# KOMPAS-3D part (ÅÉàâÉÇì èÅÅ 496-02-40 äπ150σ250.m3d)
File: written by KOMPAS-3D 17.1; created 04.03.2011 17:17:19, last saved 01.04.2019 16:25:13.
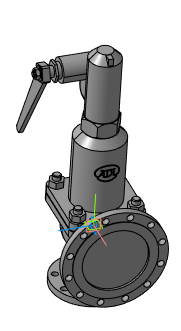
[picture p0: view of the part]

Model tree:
1. Плоскость XY
2. Плоскость ZX
3. Плоскость ZY
4. Ось X
5. Ось Y
6. Ось Z
7. Начало координат
8. Операция без истории:3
